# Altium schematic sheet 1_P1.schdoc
size 307 x 218 mm; Symbol: Drawing-Symbol_A4; Device: Drawing-Symbol_A4; @Project Name: MSDRV4; @Page Count: 1; @Update Date: 2025-03-30; @Create Date: 2025-01-27; @Schematic Name: BBC_2024_REUSE; @Page No: 1; @Page Name: P1; Company: EasyEDA.com; Version: V1.0; Page Size: A4; @Create Time: 14:20:08; @Update Time: 16:51:22; Width: 1170; Height: 825; Region Start: 1; X Region Count: 6; Y Region Count: 4; Blade Width: 10; Title Block Position: 3; @Board Name: BBC_2024_REUSE
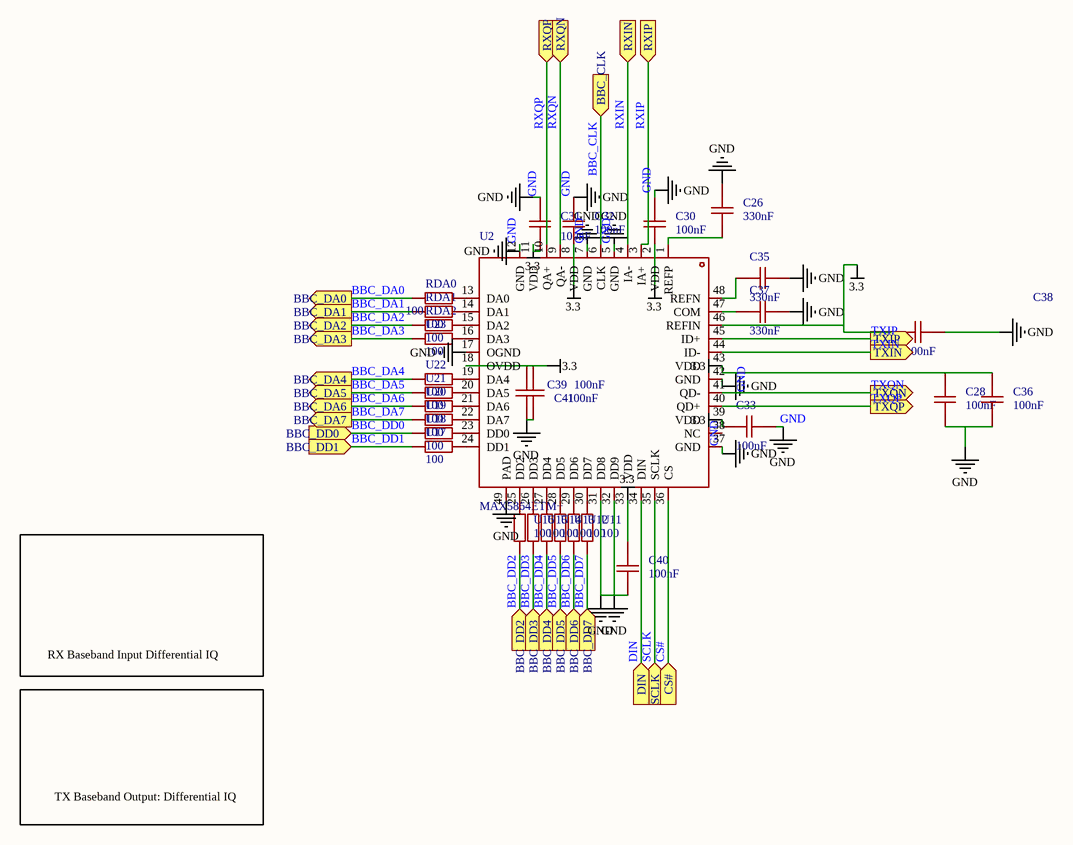
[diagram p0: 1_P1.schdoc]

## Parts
C26  330nF  [C0805]
C28  100nF  [C0805]
C30  100nF  [C0805]
C31  100nF  [C0805]
C32  100nF  [C0805]
C33  100nF  [C0805]
C35  330nF  [C0805]
C36  100nF  [C0805]
C37  330nF  [C0805]
C38  100nF  [C0805]
C39  100nF  [C0805]
C40  100nF  [C0805]
C41  100nF  [C0805]
RDA0  100  [R0805]
RDA1  100  [R0805]
RDA2  100  [R0805]
U2  MAX5864ETM+  [QFN-48_L7.0-W7.0-P0.50-BL-EP5.1]
U11  100  [R0805]
U12  100  [R0805]
U13  100  [R0805]
U14  100  [R0805]
U15  100  [R0805]
U16  100  [R0805]
U17  100  [R0805]
U18  100  [R0805]
U19  100  [R0805]
U20  100  [R0805]
U21  100  [R0805]
U22  100  [R0805]
U23  100  [R0805]

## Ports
BBC_CLK (in), BBC_DA0 (out), BBC_DA1 (out), BBC_DA2 (out), BBC_DA3 (out), BBC_DA4 (out), BBC_DA5 (out), BBC_DA6 (out), BBC_DA7 (out), BBC_DD0 (in), BBC_DD1 (in), BBC_DD2 (in), BBC_DD3 (in), BBC_DD4 (in), BBC_DD5 (in), BBC_DD6 (in), BBC_DD7 (in), CS# (in), DIN (in), RXIN (in), RXIP (in), RXQN (in), RXQP (in), SCLK (in), TXIN (out), TXIP (out), TXQN (out), TXQP (out)

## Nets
3.3: C28.2 C30.1 C31.2 C32.2 C33.1 C36.2 C38.2 C39.2 C40.2 C41.2 U2.2(VDD) U2.8(VDD) U2.11(VDD) U2.18(OVDD) U2.33(VDD) U2.39(VDD) U2.43(VDD) U2.46(REFIN)
GND: C26.1 C28.1 C30.2 C31.1 C32.1 C33.2 C35.2 C36.1 C37.1 C38.1 C39.1 C40.1 C41.1 U2.5(GND) U2.7(GND) U2.12(GND) U2.17(OGND) U2.31(DD8) U2.32(DD9) U2.37(GND) U2.41(QD-) U2.42(GND) U2.49(PAD) ; port TXQN  [also labelled TXQN]
BBC_CLK: U2.6(CLK) ; port BBC_CLK
BBC_DA0: RDA0.2 ; port BBC_DA0
BBC_DA1: RDA1.2 ; port BBC_DA1
BBC_DA2: RDA2.2 ; port BBC_DA2
BBC_DA3: U23.2 ; port BBC_DA3
BBC_DA4: U22.2 ; port BBC_DA4
BBC_DA5: U21.2 ; port BBC_DA5
BBC_DA6: U20.2 ; port BBC_DA6
BBC_DA7: U19.2 ; port BBC_DA7
BBC_DD0: U18.2 ; port BBC_DD0
BBC_DD1: U17.2 ; port BBC_DD1
BBC_DD2: U16.1 ; port BBC_DD2
BBC_DD3: U15.1 ; port BBC_DD3
BBC_DD4: U14.1 ; port BBC_DD4
BBC_DD5: U13.1 ; port BBC_DD5
BBC_DD6: U12.1 ; port BBC_DD6
BBC_DD7: U11.1 ; port BBC_DD7
CS#: U2.36(CS) ; port CS#
DIN: U2.34(DIN) ; port DIN
RXIN: U2.4(IA-) ; port RXIN
RXIP: U2.3(IA+) ; port RXIP
RXQN: U2.9(QA-) ; port RXQN
RXQP: U2.10(QA+) ; port RXQP
SCLK: U2.35(SCLK) ; port SCLK
TXIN: U2.44(ID-) ; port TXIN
TXIP: U2.45(ID+) ; port TXIP
TXQP: U2.40(QD+) ; port TXQP
NetC26_2: C26.2 U2.1(REFP)
NetC35_1: C35.1 U2.48(REFN)
NetC37_2: C37.2 U2.47(COM)
NetRDA0_1: RDA0.1 U2.13(DA0)
NetRDA1_1: RDA1.1 U2.14(DA1)
NetRDA2_1: RDA2.1 U2.15(DA2)
NetU2_16: U2.16(DA3) U23.1
NetU2_19: U2.19(DA4) U22.1
NetU2_20: U2.20(DA5) U21.1
NetU2_21: U2.21(DA6) U20.1
NetU2_22: U2.22(DA7) U19.1
NetU2_23: U2.23(DD0) U18.1
NetU2_24: U2.24(DD1) U17.1
NetU2_25: U2.25(DD2) U16.2
NetU2_26: U2.26(DD3) U15.2
NetU2_27: U2.27(DD4) U14.2
NetU2_28: U2.28(DD5) U13.2
NetU2_29: U2.29(DD6) U12.2
NetU2_30: U2.30(DD7) U11.2

Not connected (* = marked no-connect by the designer): U2 38(NC)

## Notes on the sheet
- RX Baseband Input Differential IQ
- TX Baseband Output: Differential IQ

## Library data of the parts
C26 C28 C30-C33 C35-C38 C40 = CAP_0805: Symbol: CAP; Convert to PCB: yes
C39 C41 = CAP_0805: Symbol: CAP; Convert to PCB: yes; Reuse Block: BBC_reuse; Group ID: $1e157
RDA0-RDA2 U22 U23 = 3R00: Add into BOM: yes; Reuse Block: BBC_reuse; Group ID: $1e157
U2 = MAX5864ETM+: Manufacturer: ADI(亚德诺)/MAXIM(美信); Add into BOM: yes; Supply Voltage: 2.7V~3.3V
U11-U21 = 3R00: Add into BOM: yes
